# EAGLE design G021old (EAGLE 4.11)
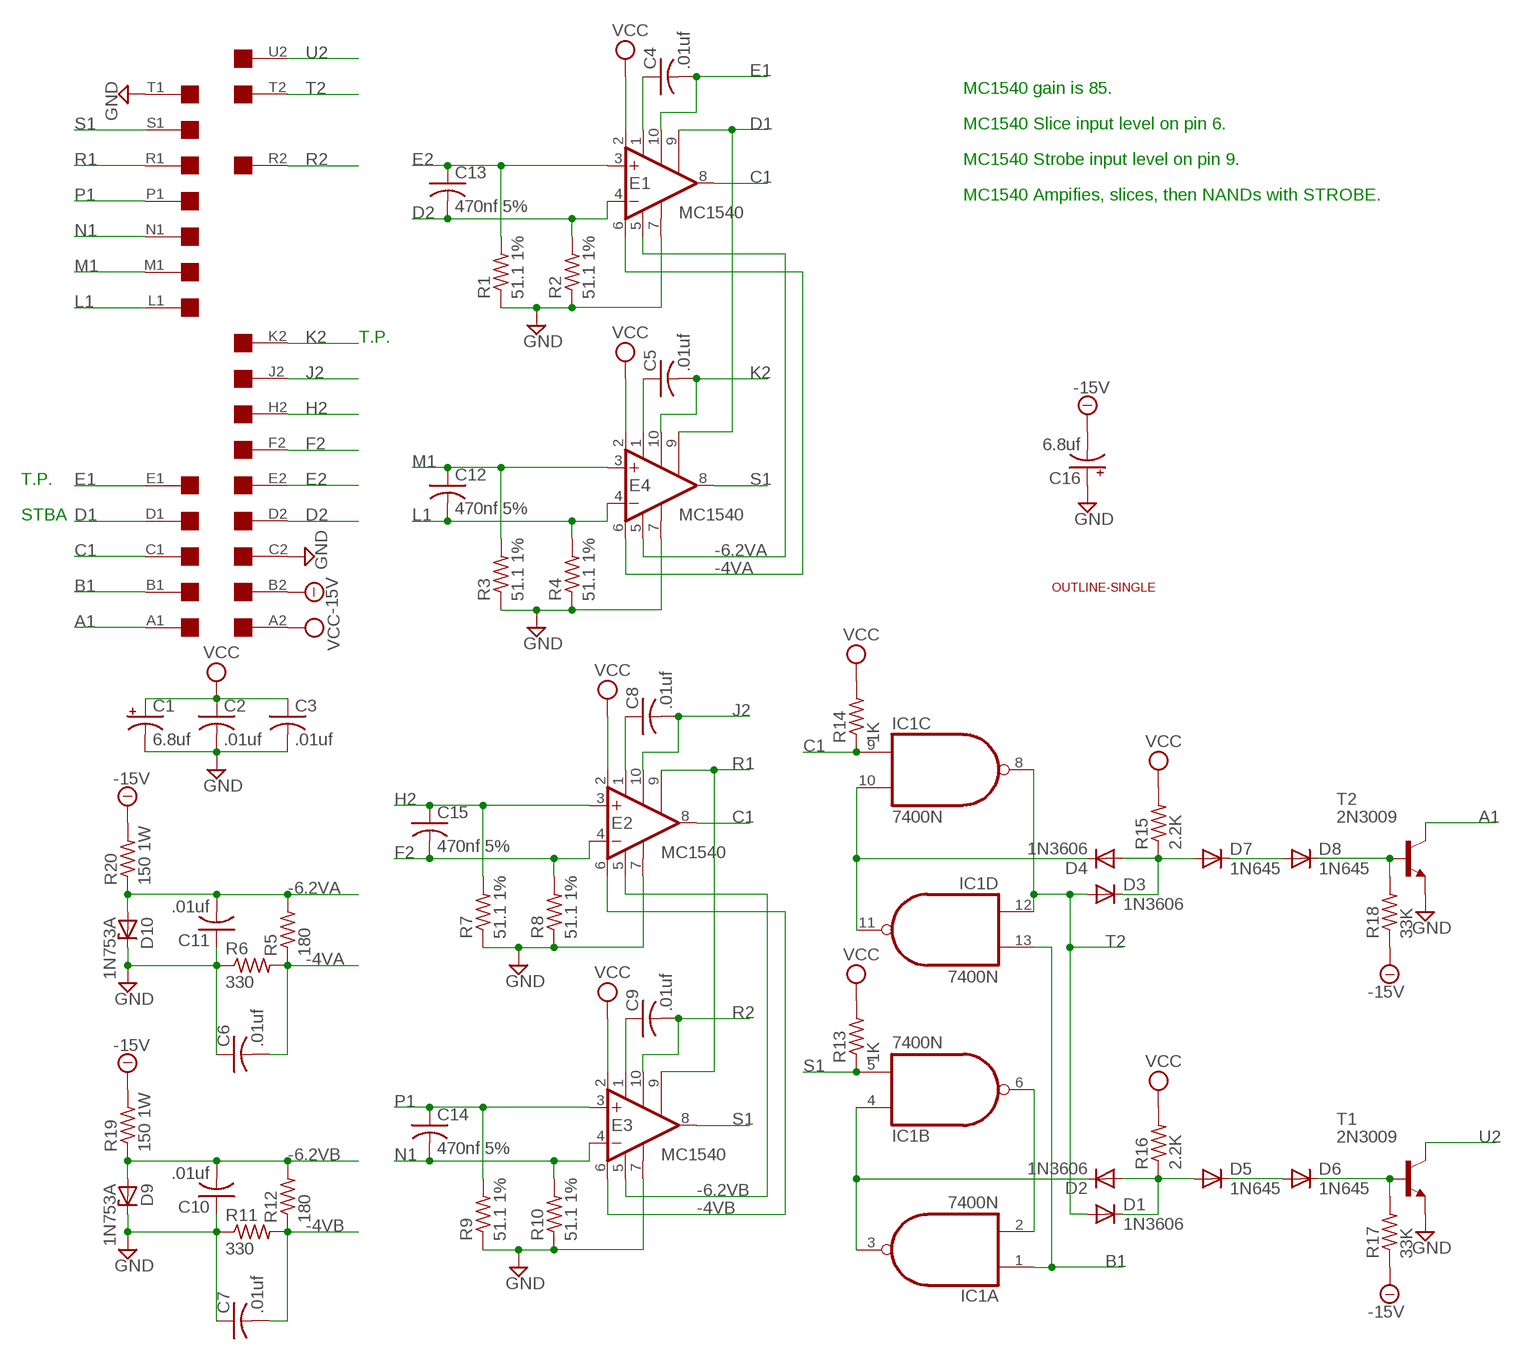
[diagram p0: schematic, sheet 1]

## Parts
C1  6.8uf  CPOL-USE15-5AXIAL  [E15-5]
C2  .01uf  C-US050-025X075  [C050-025X075]
C3  .01uf  C-US050-025X075  [C050-025X075]
C4  .01uf  C-US050-025X075  [C050-025X075]
C5  .01uf  C-US050-025X075  [C050-025X075]
C6  .01uf  C-US050-025X075  [C050-025X075]
C7  .01uf  C-US050-025X075  [C050-025X075]
C8  .01uf  C-US050-025X075  [C050-025X075]
C9  .01uf  C-US050-025X075  [C050-025X075]
C10  .01uf  C-US050-025X075  [C050-025X075]
C11  .01uf  C-US050-025X075  [C050-025X075]
C12  470nf 5%  C-US050-025X075  [C050-025X075]
C13  470nf 5%  C-US050-025X075  [C050-025X075]
C14  470nf 5%  C-US050-025X075  [C050-025X075]
C15  470nf 5%  C-US050-025X075  [C050-025X075]
C16  6.8uf  CPOL-USE15-5AXIAL  [E15-5]
D1  1N3606  1N4148  [DO35-10]
D2  1N3606  1N4148  [DO35-10]
D3  1N3606  1N4148  [DO35-10]
D4  1N3606  1N4148  [DO35-10]
D5  1N645  1N4148  [DO35-10]
D6  1N645  1N4148  [DO35-10]
D7  1N645  1N4148  [DO35-10]
D8  1N645  1N4148  [DO35-10]
D9  1N753A  ZENER-DIODEF126-10  [F126Z10]
D10  1N753A  ZENER-DIODEF126-10  [F126Z10]
E1  MC1540  [TO100]
E2  MC1540  [TO100]
E3  MC1540  [TO100]
E4  MC1540  [TO100]
IC1  7400N  [DIL14]
R1  51.1 1%  R-US_0207/10  [0207/10]
R2  51.1 1%  R-US_0207/10  [0207/10]
R3  51.1 1%  R-US_0207/10  [0207/10]
R4  51.1 1%  R-US_0207/10  [0207/10]
R5  180  R-US_0207/10  [0207/10]
R6  330  R-US_0207/10  [0207/10]
R7  51.1 1%  R-US_0207/10  [0207/10]
R8  51.1 1%  R-US_0207/10  [0207/10]
R9  51.1 1%  R-US_0207/10  [0207/10]
R10  51.1 1%  R-US_0207/10  [0207/10]
R11  330  R-US_0207/10  [0207/10]
R12  180  R-US_0207/10  [0207/10]
R13  1K  R-US_0207/10  [0207/10]
R14  1K  R-US_0207/10  [0207/10]
R15  2.2K  R-US_0207/10  [0207/10]
R16  2.2K  R-US_0207/10  [0207/10]
R17  33K  R-US_0207/10  [0207/10]
R18  33K  R-US_0207/10  [0207/10]
R19  150 1W  R-US_0414/15  [0414/15]
R20  150 1W  R-US_0414/15  [0414/15]
T1  2N3009  2N3565  [TO92]
T2  2N3009  2N3565  [TO92]
U$1  SINGLE  [EDGE-CON2]
U$2  OUTLINE-SINGLE  [SINGLE]

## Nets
-4VA: C6.2 E1.6(SLICE) E4.6(SLICE) R5.1 R6.2
-4VB: C7.2 E2.6(SLICE) E3.6(SLICE) R11.2 R12.1
-6.2VA: C11.2 D10.A E1.5(V-) E4.5(V-) R5.2 R20.1
-6.2VB: C10.2 D9.A E2.5(V-) E3.5(V-) R12.2 R19.1
-15V: C16.- R17.1 R18.1 R19.2 R20.2 U$1.B2
A1: T2.1(C) U$1.A1
B1: IC1.1(A:I0) IC1.13(D:I1) U$1.B1
C1: E1.8(OUT) E2.8(OUT) IC1.9(C:I0) R14.1 U$1.C1
D1: E1.9(ISTROBE) E4.9(ISTROBE) U$1.D1
D2: C13.2 E1.4(-IN) R2.2 U$1.D2
E1: C4.2 E1.10(CEXTB) U$1.E1
E2: C13.1 E1.3(+IN) R1.2 U$1.E2
F2: C15.2 E2.4(-IN) R8.2 U$1.F2
GND: C1.- C2.2 C3.2 C6.1 C7.1 C10.1 C11.1 C16.+ D9.C D10.C E1.7(GND) E2.7(GND) E3.7(GND) E4.7(GND) R1.1 R2.1 R3.1 R4.1 R6.1 R7.1 R8.1 R9.1 R10.1 R11.1 T1.3(E) T2.3(E) U$1.C2 U$1.T1
H2: C15.1 E2.3(+IN) R7.2 U$1.H2
J2: C8.2 E2.10(CEXTB) U$1.J2
K2: C5.2 E4.10(CEXTB) U$1.K2
L1: C12.2 E4.4(-IN) R4.2 U$1.L1
M1: C12.1 E4.3(+IN) R3.2 U$1.M1
N1: C14.2 E3.4(-IN) R10.2 U$1.N1
N$1: C4.1 E1.1(CEXTA)
N$2: C8.1 E2.1(CEXTA)
N$3: C5.1 E4.1(CEXTA)
N$4: C9.1 E3.1(CEXTA)
N$6: D1.C D2.A D5.A R16.1
N$7: D4.C IC1.10(C:I1) IC1.11(D:O)
N$8: D2.C IC1.3(A:O) IC1.4(B:I0)
N$9: IC1.2(A:I1) IC1.6(B:O)
N$10: D3.C D4.A D7.A R15.1
N$11: D7.C D8.A
N$12: D5.C D6.A
N$13: D8.C R18.2 T2.2(B)
N$14: D6.C R17.2 T1.2(B)
P1: C14.1 E3.3(+IN) R9.2 U$1.P1
R1: E2.9(ISTROBE) E3.9(ISTROBE) U$1.R1
R2: C9.2 E3.10(CEXTB) U$1.R2
S1: E3.8(OUT) E4.8(OUT) IC1.5(B:I1) R13.1 U$1.S1
T2: D1.A D3.A IC1.8(C:O) IC1.12(D:I0) U$1.T2
U2: T1.1(C) U$1.U2
VCC: C1.+ C2.1 C3.1 E1.2(V+) E2.2(V+) E3.2(V+) E4.2(V+) R13.2 R14.2 R15.2 R16.2 U$1.A2
Unconnected: U$1.F1 U$1.H1 U$1.J1 U$1.K1 U$1.L2 U$1.M2 U$1.N2 U$1.P2 U$1.S2 U$1.U1 U$1.V1 U$1.V2

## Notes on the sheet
- MC1540 gain is 85.
- MC1540 Slice input level on pin 6.
- MC1540 Strobe input level on pin 9.
- MC1540 Ampifies, slices, then NANDs with STROBE.
- T.P.
- T.P.
- STBA

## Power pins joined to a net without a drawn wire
GND: IC1.7(P:GND)
VCC: IC1.14(P:VCC)

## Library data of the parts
C1 C16 = rcl:CPOL-US: POLARIZED CAPACITOR, American symbol
C2-C15 = rcl:C-US: CAPACITOR, American symbol
D1-D8 = diode:1N4148: DIODE
D9 D10 = diode:ZENER-DIODE: Z-Diode
E1-E4 = dec-con:MC1540: OP AMP
IC1 = 74xx-us:74*00: Quad 2-input NAND gate
R1-R20 = rcl:R-US_: RESISTOR, American symbol
T1 T2 = transistor:2N3565: NPN TRANSISTOR
U$1 = dec-con:SINGLE: Double-Height DEC board
U$2 = dec-con:OUTLINE-*: Board outlines for DEC boards.

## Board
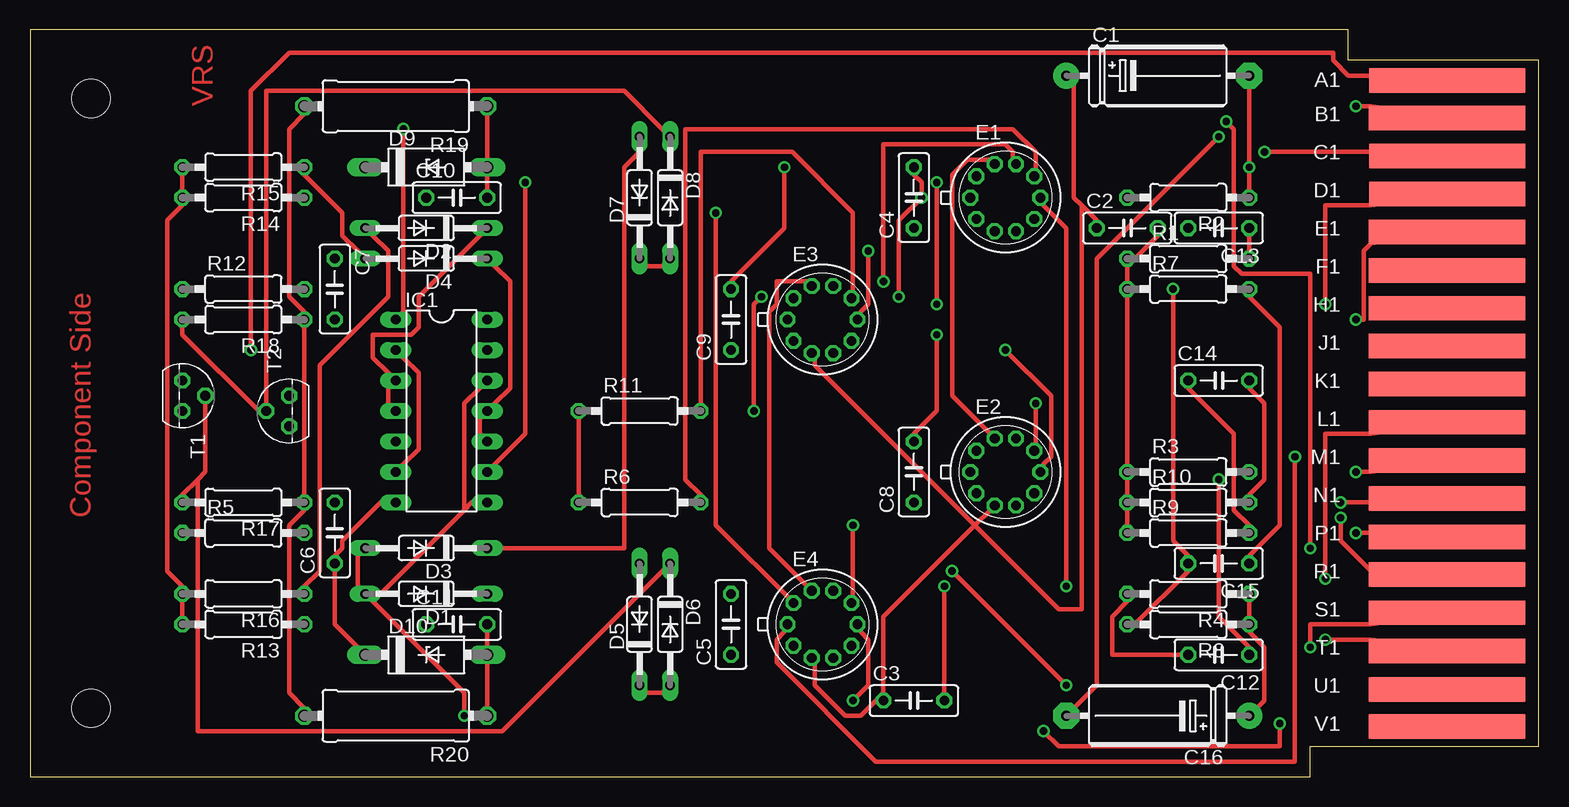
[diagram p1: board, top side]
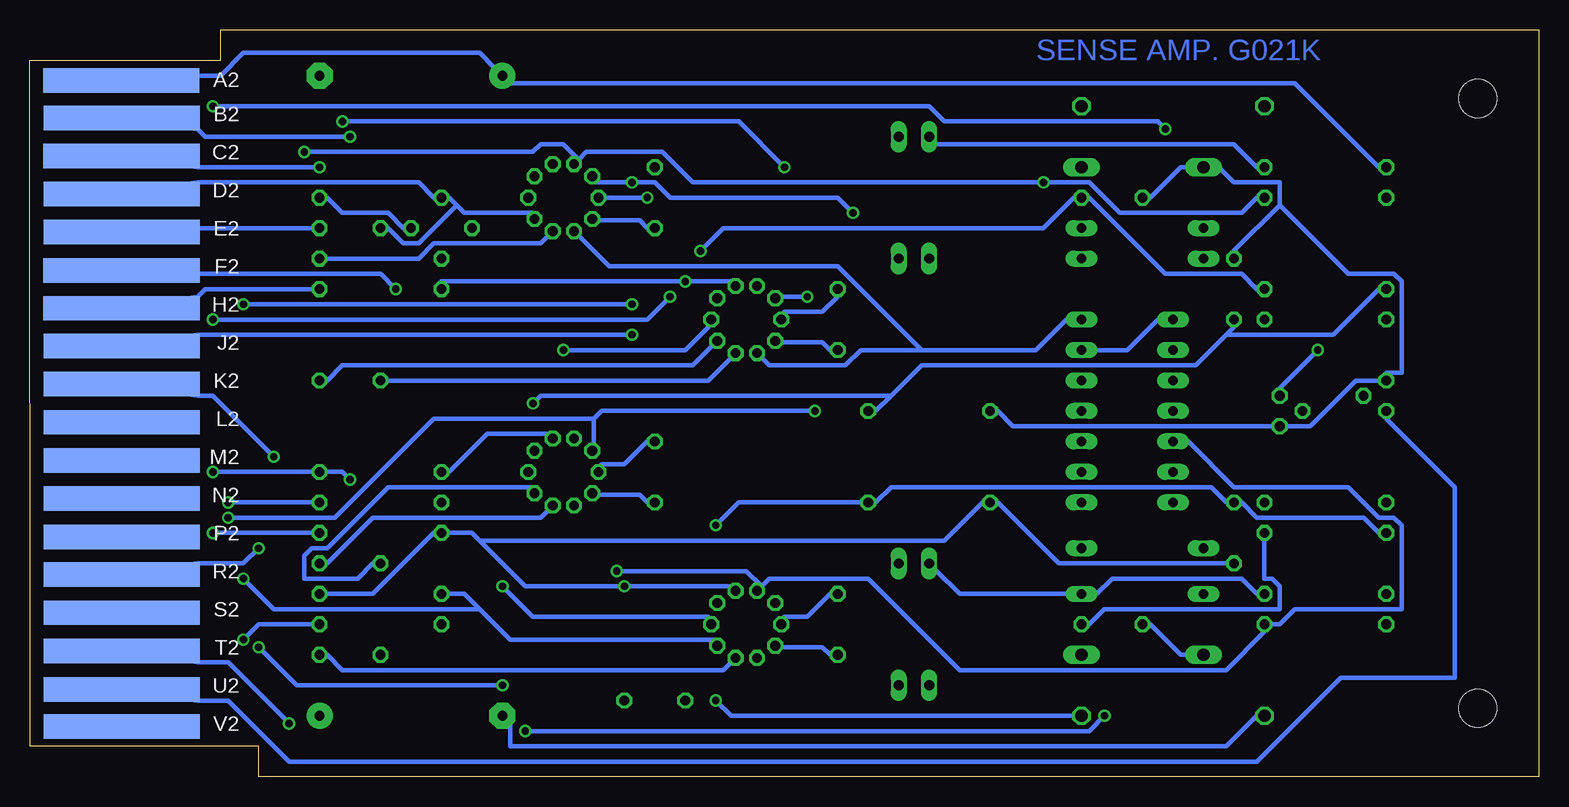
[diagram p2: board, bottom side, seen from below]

Size 125.73 x 62.23 mm. Coordinates in mm from the lower left corner, seen from the top.
Copper layers (1*16): Top 0.035mm / dielectric 1.5mm / Bottom 0.035mm
Design rules "15mils": minimum track width 15mil, minimum drill 24mil, track to track 15mil, track to pad 10mil, pad to pad 10mil, via to via 10mil, smd to smd 10mil, copper to edge 25mil, drill to drill 10mil, minimum pad ring 10mil, minimum via ring 8mil, stop-mask expansion 0mil, vias tented up to drill 0mil, thermal gap 10mil

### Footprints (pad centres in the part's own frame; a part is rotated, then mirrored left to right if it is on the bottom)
E15-5 = drill 0.813 pad 2.159 round: + -7.62,0 | drill 0.813 pad 2.159 octagon: - 7.62,0
C050-025X075 = drill 0.813 octagon: 1 -2.54,0; 2 2.54,0
DO35-10 = drill 0.813 long: A 5.08,0; C -5.08,0
F126Z10 = drill 1.016 long: A 5.08,0; C -5.08,0
TO100 = drill 0.813 octagon: 1 -2.413,-1.778; 2 -0.889,-2.794; 3 0.889,-2.794; 4 2.413,-1.778; 5 2.921,0; 6 2.413,1.778; 7 0.889,2.794; 8 -0.889,2.794; 9 -2.413,1.778; 10 -2.921,0
DIL14 = drill 0.813 long: 1 -7.62,-3.81; 2 -5.08,-3.81; 3 -2.54,-3.81; 4 0,-3.81; 5 2.54,-3.81; 6 5.08,-3.81; 7 7.62,-3.81; 8 7.62,3.81; 9 5.08,3.81; 10 2.54,3.81; 11 0,3.81; 12 -2.54,3.81; 13 -5.08,3.81; 14 -7.62,3.81
0207/10 = drill 0.813 octagon: 1 -5.08,0; 2 5.08,0
0414/15 = drill 1.016 octagon: 1 -7.62,0; 2 7.62,0
TO92 = drill 0.813 octagon: 1 1.27,0; 2 0,1.905; 3 -1.27,0
EDGE-CON2 = smd 13.017 x 2.032: A1 7.633,4.207; B1 7.639,7.327; C1 7.636,10.489; D1 7.633,13.665; E1 7.642,16.84; F1 7.642,20.041; H1 7.642,23.19; J1 7.642,26.34; K1 7.642,29.515; L1 7.642,32.69; M1 7.642,35.89; N1 7.642,39.04; P1 7.642,42.24; R1 7.642,45.39; S1 7.642,48.565; T1 7.642,51.74; U1 7.642,54.966; V1 7.642,58.026 | smd 13.017 x 2.032 bottom: A2 7.614,4.207; B2 7.642,7.328; C2 7.617,10.49; D2 7.642,13.665; E2 7.642,16.84; F2 7.617,20.041; H2 7.617,23.19; J2 7.642,26.34; K2 7.642,29.515; L2 7.642,32.69; M2 7.642,35.89; N2 7.642,39.04; P2 7.642,42.24; R2 7.642,45.39; S2 7.642,48.565; T2 7.642,51.74; U2 7.642,54.966; V2 7.642,58.026
SINGLE = hole 3.175: 120.65,56.515; 120.65,5.715

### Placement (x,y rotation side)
C1  93.98,58.42 0 top
C2  91.44,45.72 0 top
C3  73.66,6.35 0 top
C4  73.66,48.26 90 top
C5  58.42,12.7 90 top
C6  25.4,20.32 90 top
C7  25.4,40.64 270 top
C8  73.66,25.4 90 top
C9  58.42,38.1 90 top
C10  35.56,48.26 0 top
C11  35.56,12.7 0 top
C12  99.06,10.16 180 top
C13  99.06,45.72 180 top
C14  99.06,33.02 0 top
C15  99.06,17.78 180 top
C16  93.98,5.08 180 top
D1  33.02,15.24 180 top
D2  33.02,45.72 180 top
D3  33.02,19.05 180 top
D4  33.02,43.18 180 top
D5  50.8,12.7 90 top
D6  53.34,12.7 270 top
D7  50.8,48.26 90 top
D8  53.34,48.26 270 top
D9  33.02,50.8 0 top
D10  33.02,10.16 0 top
E1  81.28,48.26 0 top
E2  81.28,25.4 0 top
E3  66.04,38.1 0 top
E4  66.04,12.7 0 top
IC1  34.29,30.48 270 top
R1  96.52,43.18 0 top
R2  96.52,48.26 180 top
R3  96.52,25.4 0 top
R4  96.52,15.24 180 top
R5  17.78,20.32 0 top
R6  50.8,22.86 0 top
R7  96.52,40.64 0 top
R8  96.52,12.7 180 top
R9  96.52,20.32 0 top
R10  96.52,22.86 0 top
R11  50.8,30.48 0 top
R12  17.78,40.64 0 top
R13  17.78,12.7 180 top
R14  17.78,48.26 180 top
R15  17.78,50.8 180 top
R16  17.78,15.24 180 top
R17  17.78,22.86 180 top
R18  17.78,38.1 180 top
R19  30.48,55.88 180 top
R20  30.48,5.08 180 top
T1  12.7,31.75 270 top
T2  21.59,30.48 90 top
U$1  125.73,62.23 180 top
U$2  125.73,62.23 180 top

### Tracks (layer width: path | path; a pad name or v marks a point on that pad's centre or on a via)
-4VA  (via drill 0.61)
  Top 0.381: v68.58,20.95 68.58,14.61 E4.6 | E1.6 83.82,50.16 83.82,52.07 81.92,53.98 54.61,53.98 54.61,24.77 55.88,23.5 R6.2
  Bottom 0.381: R5.1 13.34,20.32 14.61,21.59 23.5,21.59 24.77,22.86 C6.2 26.04,22.86 27.3,24.13 53.98,24.13 55.24,22.86 R6.2 56.52,22.86 66.67,22.86 v68.58,20.95
-4VB  (via drill 0.61)
  Top 0.381: E3.6 68.58,40.01 68.58,46.99 63.5,52.07 55.88,52.07 55.88,31.11 R11.2 | v83.82,31.11 83.82,27.3 E2.6
  Bottom 0.381: 53.98,31.75 51.44,34.29 28.57,34.29 26.04,36.83 | 53.98,31.75 55.24,30.48 R11.2 | 26.04,36.83 25.4,37.47 C7.2 | 26.04,36.83 17.14,36.83 13.34,40.64 R12.1 | v83.82,31.11 83.19,31.75 53.98,31.75
-6.2VA  (via drill 0.61)
  Top 0.381: C11.2 38.1,12.06 38.1,10.79 D10.A 38.1,9.53 38.1,5.71 R20.1 | v68.58,6.35 69.85,7.62 69.85,11.43 69.22,12.06 E4.5 | v86.36,15.88 86.36,45.72 84.45,47.62 E1.5
  Bottom 0.381: R5.2 22.86,19.68 22.86,16.51 22.23,16.51 21.59,15.88 21.59,13.97 36.2,13.97 37.47,12.7 C11.2 | v68.58,6.35 67.31,5.08 38.73,5.08 R20.1 | v86.36,15.88 83.82,13.34 69.22,13.34 E4.5
-6.2VB  (via drill 0.61)
  Top 0.381: v81.28,35.56 85.09,31.75 85.09,26.67 84.45,26.04 E2.5 | C10.2 38.1,48.9 38.1,50.16 D9.A 38.1,51.44 38.1,55.24 R19.1 | v69.85,43.81 69.85,39.37 69.22,38.73 E3.5
  Bottom 0.381: v81.28,35.56 71.12,35.56 69.22,37.47 E3.5 | R12.2 23.5,40.64 24.77,41.91 31.11,41.91 37.47,48.26 C10.2 38.73,48.26 41.27,45.72 67.94,45.72 v69.85,43.81
-15V  (via drill 0.61)
  Top 0.381: R20.2 22.86,5.71 21.59,6.99 21.59,20.95 22.86,22.23 R17.1 22.86,23.5 22.86,37.47 R18.1 22.86,38.73 21.59,40.01 21.59,53.98 22.86,55.24 R19.2 | v99.06,53.34 88.9,43.18 88.9,7.62 87,5.71 C16.-
  Bottom 0.381: C16.- 85.72,4.45 85.72,2.54 26.04,2.54 23.5,5.08 R20.2 | v99.06,53.34 111.12,53.34 111.76,53.98 U$1.B2
A1  (via drill 0.61)
  Top 0.381: v18.41,35.56 18.41,57.15 21.59,60.33 108.58,60.33 108.58,59.69 109.86,58.42 111.76,58.42 U$1.A1
  Bottom 0.381: v18.41,35.56 21.59,32.38 T2.1
B1  (via drill 0.61)
  Top 0.381: v31.11,53.98 31.11,38.73 IC1.1 | v110.49,55.88 111.76,55.88 U$1.B1
  Bottom 0.381: IC1.1 31.75,38.1 34.29,35.56 36.83,35.56 IC1.13 | v31.11,53.98 31.75,54.61 49.53,54.61 50.8,55.88 v110.49,55.88
C1  (via drill 0.61)
  Top 0.381: v41.27,49.53 41.27,28.57 38.73,26.04 IC1.9 | E2.8 80.01,28.57 76.83,31.75 76.83,50.16 78.11,51.44 80.01,51.44 E1.8 | v102.87,52.07 111.76,52.07 U$1.C1
  Bottom 0.381: 80.01,51.44 79.38,52.07 73.03,52.07 70.48,49.53 v41.27,49.53 37.47,49.53 34.92,46.99 24.77,46.99 23.5,48.26 R14.1 | 80.01,51.44 E1.8 80.01,51.44 | v102.87,52.07 83.82,52.07 83.19,52.7 81.28,52.7 80.01,51.44
D1  (via drill 0.61)
  Top 0.381: v57.15,46.99 57.15,20.95 63.5,14.61 E4.9 | v107.95,39.37 107.95,47.62 111.76,47.62 U$1.D1 | v75.56,49.53 v75.56,39.37
  Bottom 0.381: v57.15,46.99 58.42,48.26 72.39,48.26 73.66,49.53 v75.56,49.53 78.74,49.53 E1.9 | v75.56,39.37 v107.95,39.37
D2
  Bottom 0.381: 90.17,47.62 90.81,48.26 R2.2 92.08,48.26 93.34,49.53 111.76,49.53 U$1.D2 | 90.17,47.62 89.53,46.99 83.82,46.99 E1.4 | 90.17,47.62 93.34,44.45 94.61,44.45 95.89,45.72 C13.2
E1  (via drill 0.61)
  Top 0.381: C4.2 73.66,50.16 74.3,49.53 v74.3,48.26 72.39,46.35 v72.39,40.01 | v110.49,38.1 111.12,38.1 111.12,43.81 111.76,44.45 U$1.E1
  Bottom 0.381: v74.3,48.26 78.11,48.26 E1.10 | v72.39,40.01 74.3,38.1 v110.49,38.1
E2
  Top 0.381: R1.2 101.6,43.81 101.6,45.09 C13.1
  Bottom 0.381: E1.3 82.55,45.09 83.19,44.45 92.08,44.45 93.34,43.18 100.97,43.18 R1.2 | C13.1 102.23,45.72 111.76,45.72 U$1.E2
F2  (via drill 0.61)
  Top 0.381: R8.2 92.08,12.7 96.52,17.14 C15.2 96.52,18.41 95.25,19.68 v95.25,40.64
  Bottom 0.381: E2.4 83.82,24.13 95.89,24.13 100.97,19.05 102.23,19.05 102.87,18.41 102.87,16.51 98.42,16.51 97.16,17.78 C15.2 | v95.25,40.64 96.52,41.91 111.76,41.91 U$1.F2
GND  (via drill 0.61)
  Top 0.381: R2.1 101.6,48.9 v101.6,50.8 101.6,57.78 C1.- | C2.2 93.98,45.09 92.08,43.18 R1.1 91.44,42.55 91.44,41.27 R7.1 91.44,40.01 91.44,26.04 R3.1 91.44,24.77 91.44,23.5 R10.1 91.44,22.23 91.44,20.95 R9.1 | v71.12,41.27 71.12,52.7 81.28,52.7 81.92,52.07 81.92,51.44 E1.7 | R6.1 45.72,23.5 45.72,29.84 R11.1 | IC1.7 29.21,22.86 26.04,19.68 26.04,19.05 25.4,18.41 C6.1 25.4,17.14 25.4,12.7 27.3,10.79 D10.C | R4.1 101.6,14.61 101.6,13.34 R8.1 101.6,12.06 102.87,10.79 102.87,6.35 102.23,5.71 C16.+ | v76.2,15.88 76.2,6.99 C3.2 | v107.95,11.43 111.76,11.43 U$1.T1
  Bottom 0.381: E3.7 67.31,41.27 v71.12,41.27 91.44,41.27 R7.1 | R2.1 100.97,48.26 99.69,46.99 95.89,46.99 94.61,45.72 C2.2 | v101.6,50.8 111.76,50.8 U$1.C2 | 21.59,47.62 25.4,43.81 C7.1 | 21.59,47.62 21.59,49.53 25.4,49.53 26.67,50.8 D9.C 29.21,50.8 29.84,50.8 32.38,48.26 C10.1 | C11.1 32.38,12.7 29.84,10.16 29.21,10.16 D10.C | C6.1 26.04,17.78 40.01,17.78 45.09,22.86 R6.1 46.35,22.86 49.53,19.68 88.27,19.68 | R11.1 45.09,30.48 43.81,29.21 22.23,29.21 T2.3 20.95,29.21 19.05,29.21 15.24,33.02 13.34,33.02 T1.3 12.7,33.66 11.43,33.66 11.43,41.27 12.06,41.91 15.88,41.91 21.59,47.62 | 88.27,19.68 88.9,20.32 90.81,20.32 R9.1 92.08,20.32 97.16,15.24 100.97,15.24 R4.1 | 88.27,19.68 84.45,15.88 v76.2,15.88 67.31,15.88 E4.7 | E2.7 82.55,28.57 87.63,28.57 90.81,25.4 R3.1 | v107.95,11.43 106.68,12.7 102.23,12.7 R8.1
H2
  Top 0.381: C15.1 101.6,18.41 104.14,20.95 104.14,37.47 101.6,40.01 R7.2
  Bottom 0.381: E2.3 82.55,22.23 83.19,21.59 97.16,21.59 100.97,17.78 C15.1 | R7.2 102.23,40.64 111.12,40.64 111.76,40.01 U$1.H2
J2  (via drill 0.61)
  Top 0.381: v75.56,36.83 75.56,30.48 73.66,28.57 C8.2
  Bottom 0.381: C8.2 74.3,27.94 76.2,26.04 78.11,26.04 E2.10 | v75.56,36.83 111.76,36.83 U$1.J2
K2  (via drill 0.61)
  Top 0.381: v105.41,26.67 105.41,1.27 70.48,1.27 62.23,9.53 62.23,11.43 62.87,12.06 E4.10
  Bottom 0.381: C5.2 59.05,15.24 60.96,13.34 62.87,13.34 E4.10 | v105.41,26.67 110.49,31.75 111.76,31.75 U$1.K2
L1  (via drill 0.61)
  Top 0.381: C12.2 95.89,10.16 90.17,10.16 90.17,13.34 91.44,14.61 R4.2 | v107.95,16.51 107.95,28.57 111.76,28.57 U$1.L1
  Bottom 0.381: 88.27,13.97 89.53,15.24 90.81,15.24 R4.2 | 88.27,13.97 85.72,11.43 68.58,11.43 E4.4 | v107.95,16.51 105.41,13.97 88.27,13.97
M1  (via drill 0.61)
  Top 0.381: v110.49,25.4 111.76,25.4 U$1.M1 | v99.06,24.77 99.06,13.34 101.6,10.79 C12.1
  Bottom 0.381: E4.3 67.31,9.53 67.94,8.89 99.69,8.89 100.97,10.16 C12.1 | v110.49,25.4 102.23,25.4 R3.2 100.97,25.4 99.69,25.4 v99.06,24.77
N1  (via drill 0.61)
  Top 0.381: R10.2 101.6,23.5 102.87,24.77 102.87,31.11 101.6,32.38 C14.2 | v109.22,22.86 111.76,22.86 U$1.N1
  Bottom 0.381: E3.4 68.58,36.2 70.48,34.29 99.69,34.29 100.97,33.02 C14.2 | v109.22,22.86 102.23,22.86 R10.2
N$1
  Bottom 0.381: C4.1 74.3,45.72 74.93,46.35 78.74,46.35 E1.1
N$2
  Bottom 0.381: C8.1 74.3,22.86 74.93,23.5 78.74,23.5 E2.1
N$3
  Bottom 0.381: C5.1 59.05,10.16 59.69,10.79 63.5,10.79 E4.1
N$4
  Bottom 0.381: C9.1 59.05,35.56 59.69,36.2 63.5,36.2 E3.1
N$6
  Top 0.381: D2.A 28.57,45.09 29.84,43.81 29.84,40.01 24.13,34.29 24.13,17.14 22.86,15.88 R16.1
  Bottom 0.381: R16.1 23.5,15.24 24.77,16.51 35.56,16.51 36.83,15.24 D1.C 39.37,15.24 48.26,15.24 50.16,17.14 D5.A
N$7
  Top 0.381: IC1.10 37.47,28.57 37.47,29.84 IC1.11 38.73,31.11 40.01,32.38 40.01,41.27 38.73,42.55 D4.C
N$8
  Top 0.381: IC1.4 29.84,31.11 29.84,32.38 IC1.3 29.84,33.66 28.57,34.92 28.57,36.83 31.75,36.83 32.38,37.47 32.38,40.01 37.47,45.09 D2.C
N$9
  Top 0.381: IC1.6 31.11,26.04 32.38,27.3 32.38,33.66 31.11,34.92 IC1.2
N$10
  Top 0.381: R15.1 22.86,50.16 26.04,46.99 26.04,45.09 27.3,43.81 D4.A | D3.C 39.37,19.05 49.53,19.05 49.53,50.8 50.8,52.07 D7.A
  Bottom 0.381: R15.1 23.5,50.8 25.4,52.7 50.16,52.7 D7.A
N$11
  Top 0.381: D7.C 51.44,42.55 52.7,42.55 D8.A
N$12
  Top 0.381: D5.C 51.44,6.99 52.7,6.99 D6.A
N$13
  Top 0.381: R18.2 12.7,37.47 12.7,36.83 19.05,30.48 T2.2 19.68,31.11 19.68,57.15 49.53,57.15 52.7,53.98 D8.C
N$14
  Top 0.381: 13.97,24.77 14.61,25.4 14.61,31.11 T1.2 | 13.97,24.77 12.7,23.5 R17.2 | 13.97,24.77 13.97,3.81 39.37,3.81 52.7,17.14 D6.C
P1  (via drill 0.61)
  Top 0.381: R9.2 101.6,20.95 100.33,22.23 100.33,28.57 96.52,32.38 C14.1 | v110.49,20.32 111.76,20.32 U$1.P1
  Bottom 0.381: E3.3 67.31,34.92 69.22,33.02 95.89,33.02 C14.1 | v110.49,20.32 102.23,20.32 R9.2
R1  (via drill 0.61)
  Top 0.381: v109.22,21.59 109.22,19.68 111.76,17.14 U$1.R1 | v60.96,40.01 60.33,39.37 v60.33,30.48
  Bottom 0.381: 78.74,29.84 78.74,27.3 E2.9 | 78.74,29.84 92.08,29.84 100.33,21.59 v109.22,21.59 | v60.96,40.01 63.5,40.01 E3.9 | v60.33,30.48 78.11,30.48 78.74,29.84
R2  (via drill 0.61)
  Top 0.381: v62.87,50.8 62.87,45.72 58.42,41.27 C9.2 | v99.69,54.61 100.33,53.98 100.33,42.55 100.97,41.91 106.68,41.91 v106.68,19.05
  Bottom 0.381: C9.2 58.42,40.01 59.69,38.73 62.87,38.73 E3.10 | v62.87,50.8 66.67,54.61 v99.69,54.61 | v106.68,19.05 107.95,17.78 111.76,17.78 U$1.R2
S1  (via drill 0.61)
  Top 0.381: E3.8 64.77,41.27 62.23,41.27 62.23,39.37 61.59,38.73 61.59,19.05 64.77,15.88 E4.8 | v106.68,10.79 106.68,12.7 111.76,12.7 U$1.S1 | v76.83,17.14 v86.36,7.62
  Bottom 0.381: 64.77,15.88 64.14,16.51 55.88,16.51 48.26,8.89 26.04,8.89 22.86,12.06 R13.1 22.23,12.7 21.59,12.7 20.32,13.97 11.43,13.97 11.43,20.95 12.06,21.59 13.34,21.59 15.88,24.13 25.4,24.13 29.21,27.94 IC1.5 | 64.77,15.88 E4.8 64.77,15.88 | v106.68,10.79 103.5,7.62 v86.36,7.62 | v76.83,17.14 66.04,17.14 64.77,15.88
T2  (via drill 0.61)
  Top 0.381: D1.A 27.3,15.88 27.3,18.41 D3.A | 36.2,22.23 29.21,15.24 D1.A | 36.2,22.23 36.83,22.86 IC1.8 | 36.2,22.23 36.2,31.11 37.47,32.38 IC1.12 | v36.2,5.08 36.2,6.99 28.57,14.61 D1.A | v84.45,3.81 85.72,2.54 104.14,2.54 v104.14,4.45
  Bottom 0.381: v36.2,5.08 37.47,3.81 v84.45,3.81 | v104.14,4.45 109.22,9.53 111.76,9.53 U$1.T2
U2
  Bottom 0.381: T1.1 12.7,29.84 6.99,24.13 6.99,8.26 16.51,8.26 23.5,1.27 104.14,1.27 109.22,6.35 111.76,6.35 U$1.U2
VCC
  Top 0.381: E4.2 65.41,9.53 65.41,7.62 67.94,5.08 69.22,5.08 70.48,6.35 C3.1 71.12,6.99 71.12,13.34 78.74,20.95 | 78.74,20.95 80.01,22.23 E2.2 | 78.74,20.95 65.41,34.29 65.41,34.92 E3.2 | R13.2 12.7,13.34 12.7,14.61 R16.2 12.7,15.88 11.43,17.14 11.43,46.35 12.7,47.62 R14.2 12.7,48.9 12.7,50.16 R15.2 | 87.63,47.62 87,48.26 87,57.78 C1.+ | 87.63,47.62 88.9,46.35 C2.1 | 78.74,20.95 85.72,13.97 87.63,13.97 87.63,47.62
  Bottom 0.381: 51.44,35.56 56.52,35.56 57.78,34.29 64.14,34.29 64.77,34.92 E3.2 | 51.44,35.56 41.91,35.56 39.37,38.1 IC1.14 | 51.44,35.56 58.42,42.55 77.47,42.55 80.01,45.09 E1.2 | U$1.A2 111.76,58.42 109.86,58.42 107.95,60.33 88.27,60.33 87,59.05 C1.+ 85.72,57.78 20.32,57.78 13.34,50.8 R15.2

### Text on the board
Top: VRS | Component Side
Bottom: SENSE AMP. G021K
